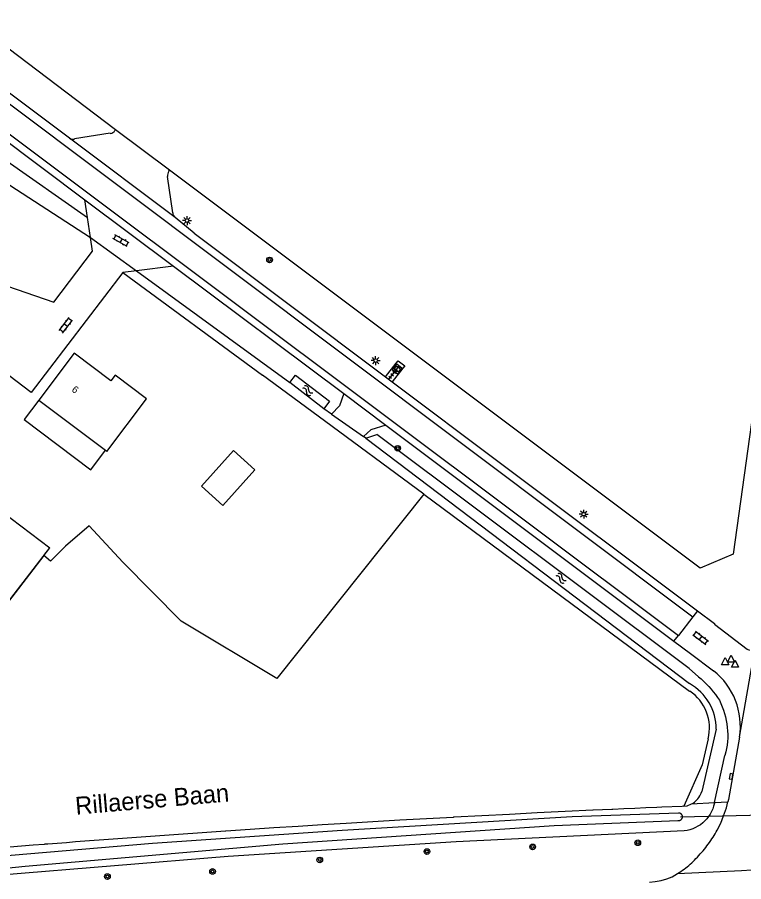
# Model space of a CAD drawing. Extents: x 126000 to 131009, y 393000 to 395500.
# Drawn here: x 130803.2 to 130905.5, y 393591.8 to 393713.6 of the extents above; entities that cross this region are included whole.
import ezdxf

# ---------------------------------------------------------------- set-up
doc = ezdxf.new("R2010")
doc.units = 0
for name, color, linetype in [('gg-afsc-hekwerk', 7, 'Continuous'), ('gg-anno-huisnummerreeks BGT', 7, 'Continuous'), ('gg-anno-openbare ruimte label', 7, 'Continuous'), ('gg-bbg-hoofdgebouw', 7, 'Continuous'), ('gg-bbg-luifel en loopbrug', 7, 'Continuous'), ('gg-knt-onverhard', 7, 'Continuous'), ('gg-knt-verharding', 7, 'Continuous'), ('gg-knt-verharding nz', 7, 'Continuous'), ('gg-kntw-bovenkant insteek waterloop', 7, 'Continuous'), ('gg-kwrk-duiker nz buis', 7, 'Continuous'), ('gt-grn-groengrens', 7, 'Continuous'), ('gt-grn-vlakafsluiter', 7, 'Continuous'), ('gt-grn-weggrens', 7, 'Continuous'), ('gt-symb-boom', 7, 'Continuous'), ('gt-symb-klinker verharding', 7, 'Continuous'), ('gt-symb-kolk', 7, 'Continuous'), ('gt-symb-lichtmast', 7, 'Continuous'), ('gt-symb-rioolschacht', 7, 'Continuous'), ('gt-symb-tegel verharding', 7, 'Continuous'), ('gt-symb-waterafsluiter', 7, 'Continuous'), ('gt-symb-watersymbool', 7, 'Continuous'), ('gx-grn-BAG pand plantopografie verbouwing', 7, 'Continuous'), ('gx-grn-maaiveld', 7, 'Continuous')]:
    doc.layers.add(name, color=color, linetype=linetype)

# ---------------------------------------------------------------- blocks, each defined once
blk = doc.blocks.new('gt0-BOOM')
at = {"layer": 'gt-symb-boom'}
for radius in [0.4, 0.2]:
    blk.add_circle((0, 0), radius, dxfattribs=at)
blk = doc.blocks.new('gt0-WA')
at = {"layer": 'gt-symb-watersymbool'}
for centre, start, end in [((-0.32, 0.02), 28.0725, 151.9275), ((0.43, 0.42), 208.0725, 331.9275), ((-0.32, -0.43), 28.0725, 151.9275), ((0.43, -0.03), 208.0725, 331.9275)]:
    blk.add_arc(centre, 0.425, start, end, dxfattribs=at)
blk = doc.blocks.new('gt0-LMAST')
at = {"layer": 'gt-symb-lichtmast'}
for p, q in [((-0.18, 0.17), (-0.45, 0.44)), ((0, 0.25), (0, 0.62)), ((0.17, 0.17), (0.44, 0.44)), ((-0.25, 0), (-0.63, 0)), ((-0.18, -0.18), (-0.45, -0.45)), ((0, -0.25), (0, -0.63)), ((0.44, -0.45), (0.17, -0.18)), ((0.25, 0), (0.62, 0))]:
    blk.add_line(p, q, dxfattribs=at)
blk.add_circle((0, 0), 0.25, dxfattribs=at)
blk = doc.blocks.new('gt0-KL1')
at = {"layer": 'gt-symb-klinker verharding'}
for p, q in [((-1.15, 0.3), (1.15, 0.3)), ((-1, -0.3), (-1, 0.3)), ((-0.5, 0.3), (-0.5, 0.45)), ((0, -0.3), (0, 0.3)), ((0.5, 0.3), (0.5, 0.45)), ((1, -0.3), (1, 0.3)), ((-1.15, -0.3), (1.15, -0.3)), ((-0.5, -0.45), (-0.5, -0.3)), ((0.5, -0.45), (0.5, -0.3))]:
    blk.add_line(p, q, dxfattribs=at)
blk = doc.blocks.new('gt0-TEG1')
at = {"layer": 'gt-symb-tegel verharding'}
for p, q in [((-1.12, 0), (1.12, 0)), ((-0.9, -0.25), (-0.9, 0.25)), ((-0.45, -0.25), (-0.45, 0.25)), ((0, -0.25), (0, 0.25)), ((0.45, -0.25), (0.45, 0.25)), ((0.9, -0.25), (0.9, 0.25))]:
    blk.add_line(p, q, dxfattribs=at)
blk = doc.blocks.new('gt0-RS')
at = {"layer": 'gt-symb-rioolschacht'}
blk.add_lwpolyline([(-0.5, -0.5), (0.5, -0.5), (0.5, 0.5), (-0.5, 0.5)], close=True, dxfattribs=at)
blk.add_circle((0, 0), 0.375, dxfattribs=at)
blk = doc.blocks.new('gt0-WAFSL')
at = {"layer": 'gt-symb-waterafsluiter'}
for p, q in [((-0.5, -0.33), (0, 0.67)), ((0, 0.67), (0.5, -0.33)), ((0.5, -0.33), (-0.5, -0.33))]:
    blk.add_line(p, q, dxfattribs=at)
blk = doc.blocks.new('gt0-KOLK')
at = {"layer": 'gt-symb-kolk'}
blk.add_lwpolyline([(0, 0), (0.38, 0), (0.38, 0.4), (-0.37, 0.4), (-0.37, 0), (0, 0)], dxfattribs=at)

msp = doc.modelspace()

# ---------------------------------------------------------------- linework, layer by layer
at = {"layer": 'gg-afsc-hekwerk'}
msp.add_line((130824.64, 393692.08), (130817.03, 393697.79), dxfattribs=at)
for points in [[(130817.03, 393697.79), (130800.42, 393710.29), (130800.7, 393710.61)], [(130911.77, 393693.29), (130904.07, 393637.95), (130899.41, 393635.98), (130824.64, 393692.08)]]:
    msp.add_lwpolyline(points, dxfattribs=at)
at = {"layer": 'gg-bbg-hoofdgebouw'}
for p, q in [((130806.22, 393659.68), (130815.59, 393652.61)), ((130815.59, 393652.61), (130815.8, 393652.45))]:
    msp.add_line(p, q, dxfattribs=at)
msp.add_lwpolyline([(130815.8, 393652.45), (130821.38, 393659.84), (130816.95, 393663.18), (130816.36, 393662.39), (130811.21, 393666.28), (130806.22, 393659.68)], dxfattribs=at)
at = {"layer": 'gg-bbg-luifel en loopbrug'}
for points in [[(130806.22, 393659.68), (130804.15, 393656.94), (130813.53, 393649.87), (130815.59, 393652.61)], [(130829.12, 393647.54), (130833.66, 393652.56), (130836.66, 393649.85), (130832.12, 393644.83), (130829.12, 393647.54)]]:
    msp.add_lwpolyline(points, dxfattribs=at)
at = {"layer": 'gg-knt-onverhard'}
for points in [[(130849.17, 393660.6), (130848.56, 393658.87), (130847.46, 393657.69)], [(130855.09, 393656.16), (130853, 393655.47), (130851.96, 393654.55)]]:
    msp.add_lwpolyline(points, dxfattribs=at)
at = {"layer": 'gg-knt-verharding'}
for p, q in [((130781, 393711.7), (130812.71, 393687.91)), ((130816.28, 393697.28), (130811.23, 393696.48)), ((130816.94, 393697.67), (130817.03, 393697.79)), ((130824.54, 393691.95), (130824.64, 393692.08)), ((130825.08, 393686.07), (130824.35, 393691.21)), ((130812.71, 393687.91), (130825.21, 393678.55)), ((130813.07, 393685.41), (130812.71, 393687.91)), ((130813.48, 393682.61), (130813.07, 393685.41)), ((130828.08, 393683.19), (130825.43, 393685.41)), ((130828.08, 393683.19), (130855.05, 393662.97)), ((130825.21, 393678.55), (130819.97, 393677.89)), ((130825.21, 393678.55), (130849.17, 393660.6)), ((130819.97, 393677.89), (130818.07, 393677.65)), ((130855.05, 393662.97), (130856.56, 393664.89)), ((130857.53, 393664.17), (130856.02, 393662.24)), ((130856.02, 393662.24), (130871.27, 393650.81)), ((130849.17, 393660.6), (130855.09, 393656.16)), ((130855.09, 393656.16), (130895.72, 393625.72)), ((130871.27, 393650.81), (130899.05, 393629.99)), ((130895.72, 393625.72), (130898.06, 393623.97)), ((130898.06, 393623.97), (130901.31, 393621.55)), ((130904.97, 393612.18), (130907.17, 393624.8))]:
    msp.add_line(p, q, dxfattribs=at)
for points in [[(130810.53, 393696.61), (130800.52, 393704.08), (130789.5, 393712.43)], [(130790.91, 393672.53), (130795.06, 393678.03), (130808.33, 393673.49), (130813.76, 393680.68), (130813.48, 393682.61)], [(130818.07, 393677.65), (130805.14, 393660.73), (130799.96, 393664.65)], [(130856.56, 393664.89), (130856.83, 393665.23), (130857.81, 393664.53), (130857.53, 393664.17)], [(130899.05, 393629.99), (130901.43, 393628.2), (130901.44, 393628.09), (130906.02, 393624.59), (130906.36, 393624.43)], [(130904.97, 393612.18), (130903.4, 393603.4), (130903.31, 393603.06)]]:
    msp.add_lwpolyline(points, dxfattribs=at)
for centre, radius, start, end in [((130816.26, 393698.06), 0.785, 271.5068, 329.6222), ((130811.02, 393697.28), 0.835, 233.8695, 284.7637), ((130825.42, 393691.33), 1.07, 145.0044, 186.6318), ((130825.98, 393686.12), 0.901, 183.3928, 232.3459), ((130895.06, 393613.71), 10.02, 351.2078, 51.4343)]:
    msp.add_arc(centre, radius, start, end, dxfattribs=at)
at = {"layer": 'gg-knt-verharding nz'}
for p, q in [((130633.6, 393827.89), (130898.38, 393629.14)), ((130825.43, 393685.41), (130810.53, 393696.61)), ((130899.05, 393629.99), (130898.38, 393629.14)), ((130895.72, 393625.72), (130896.35, 393626.52))]:
    msp.add_line(p, q, dxfattribs=at)
msp.add_lwpolyline([(130628.56, 393821.67), (130636.11, 393820.63), (130641.9, 393817.25), (130896.35, 393626.52)], dxfattribs=at)
at = {"layer": 'gg-kntw-bovenkant insteek waterloop'}
for p, q in [((130846.36, 393658.46), (130841.57, 393662.15)), ((130852.28, 393654.32), (130853.82, 393654.84)), ((130852.28, 393654.32), (130897.91, 393619.72)), ((130901.67, 393613.29), (130899.63, 393604.52)), ((130901.43, 393602.96), (130902.89, 393609.61))]:
    msp.add_line(p, q, dxfattribs=at)
for points in [[(130841.57, 393662.15), (130842.39, 393663.21), (130847.17, 393659.51), (130846.36, 393658.46)], [(130899.16, 393620.7), (130897.88, 393621.86), (130853.82, 393654.84)]]:
    msp.add_lwpolyline(points, dxfattribs=at)
msp.add_arc((130894.36, 393613.33), 7.31, 359.6327, 60.9211, dxfattribs=at)
at = {"layer": 'gg-kwrk-duiker nz buis'}
msp.add_line((130896.65, 393600.95), (130920.55, 393601.49), dxfattribs=at)
at = {"layer": 'gt-grn-groengrens'}
for p, q in [((130801.29, 393693.68), (130813.07, 393685.41)), ((130798.51, 393692.3), (130813.48, 393682.61)), ((130819.97, 393677.89), (130841.57, 393662.15)), ((130847.46, 393657.69), (130846.36, 393658.46)), ((130852.28, 393654.32), (130851.96, 393654.55))]:
    msp.add_line(p, q, dxfattribs=at)
at = {"layer": 'gt-grn-vlakafsluiter'}
for p, q in [((130847.46, 393657.69), (130851.96, 393654.55)), ((130898.21, 393602.78), (130901.43, 393602.96)), ((130901.43, 393602.96), (130903.31, 393603.06))]:
    msp.add_line(p, q, dxfattribs=at)
at = {"layer": 'gt-grn-weggrens'}
for p, q in [((130813.48, 393682.61), (130819.97, 393677.89)), ((130855.05, 393662.97), (130856.02, 393662.24)), ((130898.38, 393629.14), (130896.35, 393626.52))]:
    msp.add_line(p, q, dxfattribs=at)
at = {"layer": 'gx-grn-BAG pand plantopografie verbouwing'}
msp.add_line((130797.88, 393626.07), (130807.75, 393638.88), dxfattribs=at)
at = {"layer": 'gx-grn-maaiveld'}
for p, q in [((130818.07, 393677.65), (130837.75, 393663.19)), ((130860.46, 393646.42), (130897.93, 393618.68)), ((130806.9, 393637.77), (130807.75, 393638.88)), ((130806.9, 393637.77), (130797.88, 393626.07)), ((130899.16, 393620.7), (130899.54, 393620.38)), ((130899.54, 393620.38), (130899.91, 393620.04)), ((130899.91, 393620.04), (130900.26, 393619.7)), ((130900.26, 393619.7), (130900.61, 393619.34)), ((130900.61, 393619.34), (130900.94, 393618.96)), ((130900.94, 393618.96), (130901.26, 393618.58)), ((130901.26, 393618.58), (130901.56, 393618.19)), ((130901.56, 393618.19), (130901.86, 393617.78)), ((130901.86, 393617.78), (130902.13, 393617.37)), ((130902.13, 393617.37), (130902.34, 393616.92)), ((130902.34, 393616.92), (130902.53, 393616.46)), ((130902.53, 393616.46), (130902.7, 393615.99)), ((130902.7, 393615.99), (130902.85, 393615.51)), ((130902.85, 393615.51), (130902.98, 393615.03)), ((130902.98, 393615.03), (130903.08, 393614.54)), ((130903.08, 393614.54), (130903.16, 393614.05)), ((130903.16, 393614.05), (130903.23, 393613.56)), ((130903.23, 393613.56), (130903.27, 393613.06)), ((130903.27, 393613.06), (130903.3, 393612.56)), ((130903.28, 393611.57), (130903.23, 393611.07)), ((130903.3, 393612.06), (130903.28, 393611.57)), ((130903.3, 393612.56), (130903.3, 393612.06)), ((130903.14, 393610.58), (130903.03, 393610.09)), ((130903.23, 393611.07), (130903.14, 393610.58)), ((130903.03, 393610.09), (130902.89, 393609.61))]:
    msp.add_line(p, q, dxfattribs=at)
for points in [[(130860.46, 393646.42), (130845.59, 393657.43), (130837.75, 393663.19)], [(130797.88, 393626.07), (130787.24, 393634.51), (130796.79, 393647.15), (130807.75, 393638.88)], [(130860.46, 393646.42), (130839.76, 393620.44), (130826.27, 393628.51), (130818.06, 393636.85), (130813.29, 393641.98), (130809.98, 393639.11), (130807.87, 393637), (130806.9, 393637.77)], [(130900.52, 393611.94), (130899.67, 393608.3), (130897.09, 393602.44)], [(130898.21, 393602.78), (130898.41, 393602.9), (130898.6, 393603.03), (130898.77, 393603.18), (130898.94, 393603.34), (130899.09, 393603.51), (130899.23, 393603.69), (130899.36, 393603.89), (130899.46, 393604.09), (130899.56, 393604.3), (130899.63, 393604.52)], [(130901.43, 393602.96), (130901.41, 393602.87), (130901.31, 393602.47), (130901.18, 393602.08), (130901.02, 393601.7), (130900.83, 393601.34), (130900.63, 393601.04), (130900.6, 393601), (130900.35, 393600.67), (130900.07, 393600.37), (130899.77, 393600.09), (130899.45, 393599.84), (130899.1, 393599.62), (130898.74, 393599.43), (130898.36, 393599.27), (130897.97, 393599.14), (130897.58, 393599.04), (130897.17, 393598.98), (130865.03, 393597.45), (130832.91, 393595.37), (130800.84, 393592.73), (130735.77, 393585.08)], [(130896.2, 393592.96), (130896.44, 393593.11), (130896.68, 393593.26), (130896.91, 393593.42), (130897.14, 393593.58), (130897.37, 393593.74), (130897.59, 393593.92), (130897.81, 393594.1), (130898.02, 393594.28), (130898.23, 393594.47), (130898.43, 393594.66), (130898.63, 393594.86), (130898.82, 393595.07), (130899.03, 393595.28), (130899.23, 393595.5), (130899.43, 393595.72), (130899.62, 393595.94), (130899.82, 393596.17), (130900, 393596.39), (130900.19, 393596.63), (130900.37, 393596.87), (130900.55, 393597.11), (130900.73, 393597.35), (130900.9, 393597.6), (130901.06, 393597.84), (130901.22, 393598.08), (130901.37, 393598.33), (130901.52, 393598.57), (130901.66, 393598.82), (130901.8, 393599.07), (130902.3, 393600.06), (130902.72, 393601.09), (130903.1, 393602.23), (130903.31, 393603.06)], [(130897.09, 393602.44), (130896.89, 393602.41), (130894, 393602.29), (130893.3, 393602.26), (130891.74, 393602.2), (130890.19, 393602.13), (130888.63, 393602.06), (130887.08, 393601.99), (130886.94, 393601.99), (130884.33, 393601.87), (130884.29, 393601.87), (130880.38, 393601.68), (130876.46, 393601.5), (130872.55, 393601.3), (130868.64, 393601.1), (130864.73, 393600.89), (130864.67, 393600.89), (130864.61, 393600.88), (130860.84, 393600.68), (130857.07, 393600.46), (130853.3, 393600.24), (130849.52, 393600.02), (130849.51, 393600.02), (130846.12, 393599.81), (130842.74, 393599.6), (130839.35, 393599.38), (130835.97, 393599.16), (130832.58, 393598.94), (130832.57, 393598.93), (130832.52, 393598.93), (130829.21, 393598.71), (130825.91, 393598.48), (130822.61, 393598.24), (130819.31, 393598), (130816.01, 393597.76), (130812.71, 393597.51), (130812.69, 393597.51), (130811.39, 393597.41), (130810.09, 393597.31), (130808.79, 393597.21), (130807.5, 393597.11), (130807.05, 393597.08), (130806.96, 393597.07), (130805.41, 393596.95), (130803.76, 393596.82), (130802.11, 393596.68)], [(130897.09, 393602.44), (130897.57, 393602.52), (130898.21, 393602.78)], [(130896.34, 393601.48), (130881.35, 393600.94), (130848.94, 393599.01), (130822.23, 393597.17), (130802.29, 393595.49), (130769.4, 393592.29), (130745.21, 393589.53)], [(130770.93, 393590.56), (130804.3, 393594.01), (130840.58, 393597.15), (130878.84, 393599.71), (130896.26, 393600.45), (130896.3, 393600.44), (130896.35, 393600.43), (130896.39, 393600.43), (130896.44, 393600.43), (130896.48, 393600.44), (130896.53, 393600.45), (130896.57, 393600.47), (130896.61, 393600.48), (130896.65, 393600.5), (130896.69, 393600.53), (130896.73, 393600.56), (130896.76, 393600.59), (130896.79, 393600.62), (130896.82, 393600.66), (130896.85, 393600.7), (130896.87, 393600.74), (130896.88, 393600.78), (130896.9, 393600.82), (130896.91, 393600.87), (130896.91, 393600.92), (130896.91, 393600.95), (130896.91, 393600.96), (130896.91, 393601.01), (130896.91, 393601.05), (130896.9, 393601.1), (130896.88, 393601.14), (130896.86, 393601.18), (130896.84, 393601.22), (130896.82, 393601.26), (130896.79, 393601.3), (130896.76, 393601.33), (130896.72, 393601.36), (130896.69, 393601.39), (130896.65, 393601.41), (130896.61, 393601.43), (130896.57, 393601.45), (130896.52, 393601.47), (130896.48, 393601.48), (130896.43, 393601.48), (130896.39, 393601.48), (130896.34, 393601.48)], [(130896.2, 393592.96), (130896.2, 393592.96), (130905.22, 393593.39), (130906.67, 393593.46), (130921.58, 393594.16)], [(130892.26, 393591.72), (130893.09, 393591.82), (130893.9, 393591.98), (130894.7, 393592.21), (130895.47, 393592.51), (130896.2, 393592.96)]]:
    msp.add_lwpolyline(points, dxfattribs=at)
msp.add_arc((130894.49, 393613.49), 6.23, 345.5919, 56.4193, dxfattribs=at)

# ---------------------------------------------------------------- block references
at = {"layer": 'gt-symb-boom'}
for p in [(130838.73, 393679.43), (130856.78, 393652.89), (130875.8, 393596.71), (130890.62, 393597.29), (130860.91, 393596.05), (130845.8, 393594.87), (130830.69, 393593.26), (130815.87, 393592.53)]:
    msp.add_blockref('gt0-BOOM', p, dxfattribs=at)
at = {"layer": 'gt-symb-klinker verharding'}
for p, rotation in [((130817.79, 393682.16), 150.20538279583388), ((130810.01, 393670.22), 52.602679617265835), ((130899.49, 393626.17), -36.869897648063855)]:
    msp.add_blockref('gt0-KL1', p, dxfattribs=dict(at, rotation=rotation))
at = {"layer": 'gt-symb-kolk', "rotation": 79.85920685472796}
msp.add_blockref('gt0-KOLK', (130903.97, 393606.61), dxfattribs=at)
at = {"layer": 'gt-symb-lichtmast'}
for p in [(130827.1, 393684.98), (130853.67, 393665.25), (130883, 393643.61)]:
    msp.add_blockref('gt0-LMAST', p, dxfattribs=at)
at = {"layer": 'gt-symb-rioolschacht', "rotation": -130.78156719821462}
msp.add_blockref('gt0-RS', (130856.73, 393664.06), dxfattribs=at)
at = {"layer": 'gt-symb-tegel verharding', "rotation": 52.10993718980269}
msp.add_blockref('gt0-TEG1', (130856.28, 393663.57), dxfattribs=at)
at = {"layer": 'gt-symb-waterafsluiter'}
for p in [(130903.77, 393623.08), (130902.94, 393622.72), (130904.33, 393622.36)]:
    msp.add_blockref('gt0-WAFSL', p, dxfattribs=at)
at = {"layer": 'gt-symb-watersymbool'}
for p, rotation in [((130844.04, 393661.06), -39.1966888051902), ((130879.75, 393634.61), -39.196688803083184)]:
    msp.add_blockref('gt0-WA', p, dxfattribs=dict(at, rotation=rotation))

# ---------------------------------------------------------------- texts
at = {"layer": 'gg-anno-huisnummerreeks BGT'}
msp.add_text('6', height=1, rotation=322.9, dxfattribs=at).set_placement((130810.75, 393660.99))
at = {"layer": 'gg-anno-openbare ruimte label'}
msp.add_text('Rillaerse Baan', height=2.5, rotation=5, dxfattribs=at).set_placement((130811.45, 393601.24))

doc.saveas('drawing.dxf')
